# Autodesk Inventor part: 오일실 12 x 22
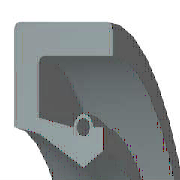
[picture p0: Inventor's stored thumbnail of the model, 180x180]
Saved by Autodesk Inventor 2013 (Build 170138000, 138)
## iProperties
IsCustomPart: 0
Created: 2015-10
Part Number: 오일실 12 x 22
Material: 고무
Description: 오일-실
Document SubType Name: Modeling
Standard: KS B 2804
Designer: mdu
Standards Organization: KS
Language: ko-KR
Size Designation: S - 12 22 7
Categories: <MemberInstance><Categories><Category DisplayName="샤프트 부품" InternalName="7f7aeb1f-a693-4053-b835-cee3144e0d98" Mnemonic="SHFT"><Category DisplayName="실링" Intern
Density: 0.93 g/cm^3
Author: mdu
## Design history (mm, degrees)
revolve "본체" stored, may be unused: angle "d17" = 90 deg
revolve "스프링1" stored, may be unused: angle "d18" = 90 deg
body "Solid1"
sketch "스케치1"
  geometry: L1 (0, 11)-(7, 11); L2 (7, 11)-(7, 9.75); L3 (7, 9.75)-(1.75, 9.75); L4 (0, 11)-(0, 8.1); L5 (0, 8.1)-(1.75, 7.75); L6 (1.75, 7.75)-(4.9, 6); L7 (4.9, 6)-(0, 6); L8 (6.3, 6.875)-(6.3, 8.1); L9 (0, 0)-(9.586, 0) reference; L10 (4.9, 6)-(6.3, 6.875); L11 (0, 18)-(0, -3) reference; L12 (-1.917, 0)-(11.503, 0) reference; L13 (4.2, 8.1)-(1.75, 8.59); L14 (1.75, 8.59)-(1.75, 9.75); L15 (6.3, 8.1)-(5.6, 8.1); C1 r 0.455 at (4.9, 8.1); A1 r 0.7 centre (4.9, 8.1) between (5.6, 8.1) and (4.2, 8.1)
  constraints: 26 end point, 5 horizontal alignment, 4 perpendicular, 2 centre point, 2 collinear, 2 horizontal, 2 parallel, 2 point on circle, 2 point on line, 2 vertical alignment, 1 coincident
  dimensions: "d0" = 22 diameter of L1 L9 (= SD2); "d1" = 13.75 diameter of L8.start L9 (= ABDM); "d2" = 1.25 distance of L1.end L2.end (computed from SD); "d3" = 0.91 diameter of C1 (= SPDI); "d4" = 1.4 diameter of A1 (= SPDA); "d5" = 12 diameter of L6.end L9 (= NND); "d6" = 15.5 diameter of L5.end L9 (= TKDM); "d7" = 16.2 diameter of L4.end L9 (= HLDM); "d8" = 4.9 distance from line of C1.centre L4 (= SPDST); "d9" = 6.3 distance between parallel lines of L8 L4 (= SDI); "d10" = 7 distance between parallel lines of L2 L4 (= SWDT); "d12" = 1.75 distance between parallel lines of L14 L4 (= SD)
fillet "모깎기1" dims "d11" = 0.3 (= RR)
other parameters: "SD2" = 22 [user parameter; used in 1 equation term], "SWDT" = 7 [user parameter; used in 1 equation term], "RR" = 0.3 [user parameter; used in 1 equation term], "SD" = 1.75 [user parameter; used in 2 equation terms], "NND" = 12 [user parameter; used in 1 equation term], "SPDA" = 1.4 [user parameter; used in 1 equation term], "SPDI" = 0.91 [user parameter; used in 1 equation term], "TKDM" = 15.5 [user parameter; used in 1 equation term], "HLDM" = 16.2 [user parameter; used in 1 equation term], "ABDM" = 13.75 [user parameter; used in 1 equation term], "SDI" = 6.3 [user parameter; used in 1 equation term], "SPDST" = 4.9 [user parameter; used in 1 equation term], "d13" = 0, "d14" = 0, "d15" = 0, "LAB" = 0.35 [user parameter]
